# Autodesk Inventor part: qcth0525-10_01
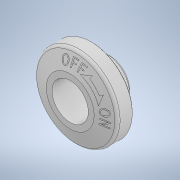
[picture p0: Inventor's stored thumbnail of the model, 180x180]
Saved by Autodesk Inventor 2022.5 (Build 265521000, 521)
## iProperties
Created: 2022-02
Part Number: qcth0525-10_01
Material: 一般
Document SubType Name: Modeling
Designer: ImaoCorp
Density: 1 g/cm^3
Appearance: 既定
Author: ImaoCorp
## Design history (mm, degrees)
feature "qcth0525-10_01"
node "ソリッド1"
